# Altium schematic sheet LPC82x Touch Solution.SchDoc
size B
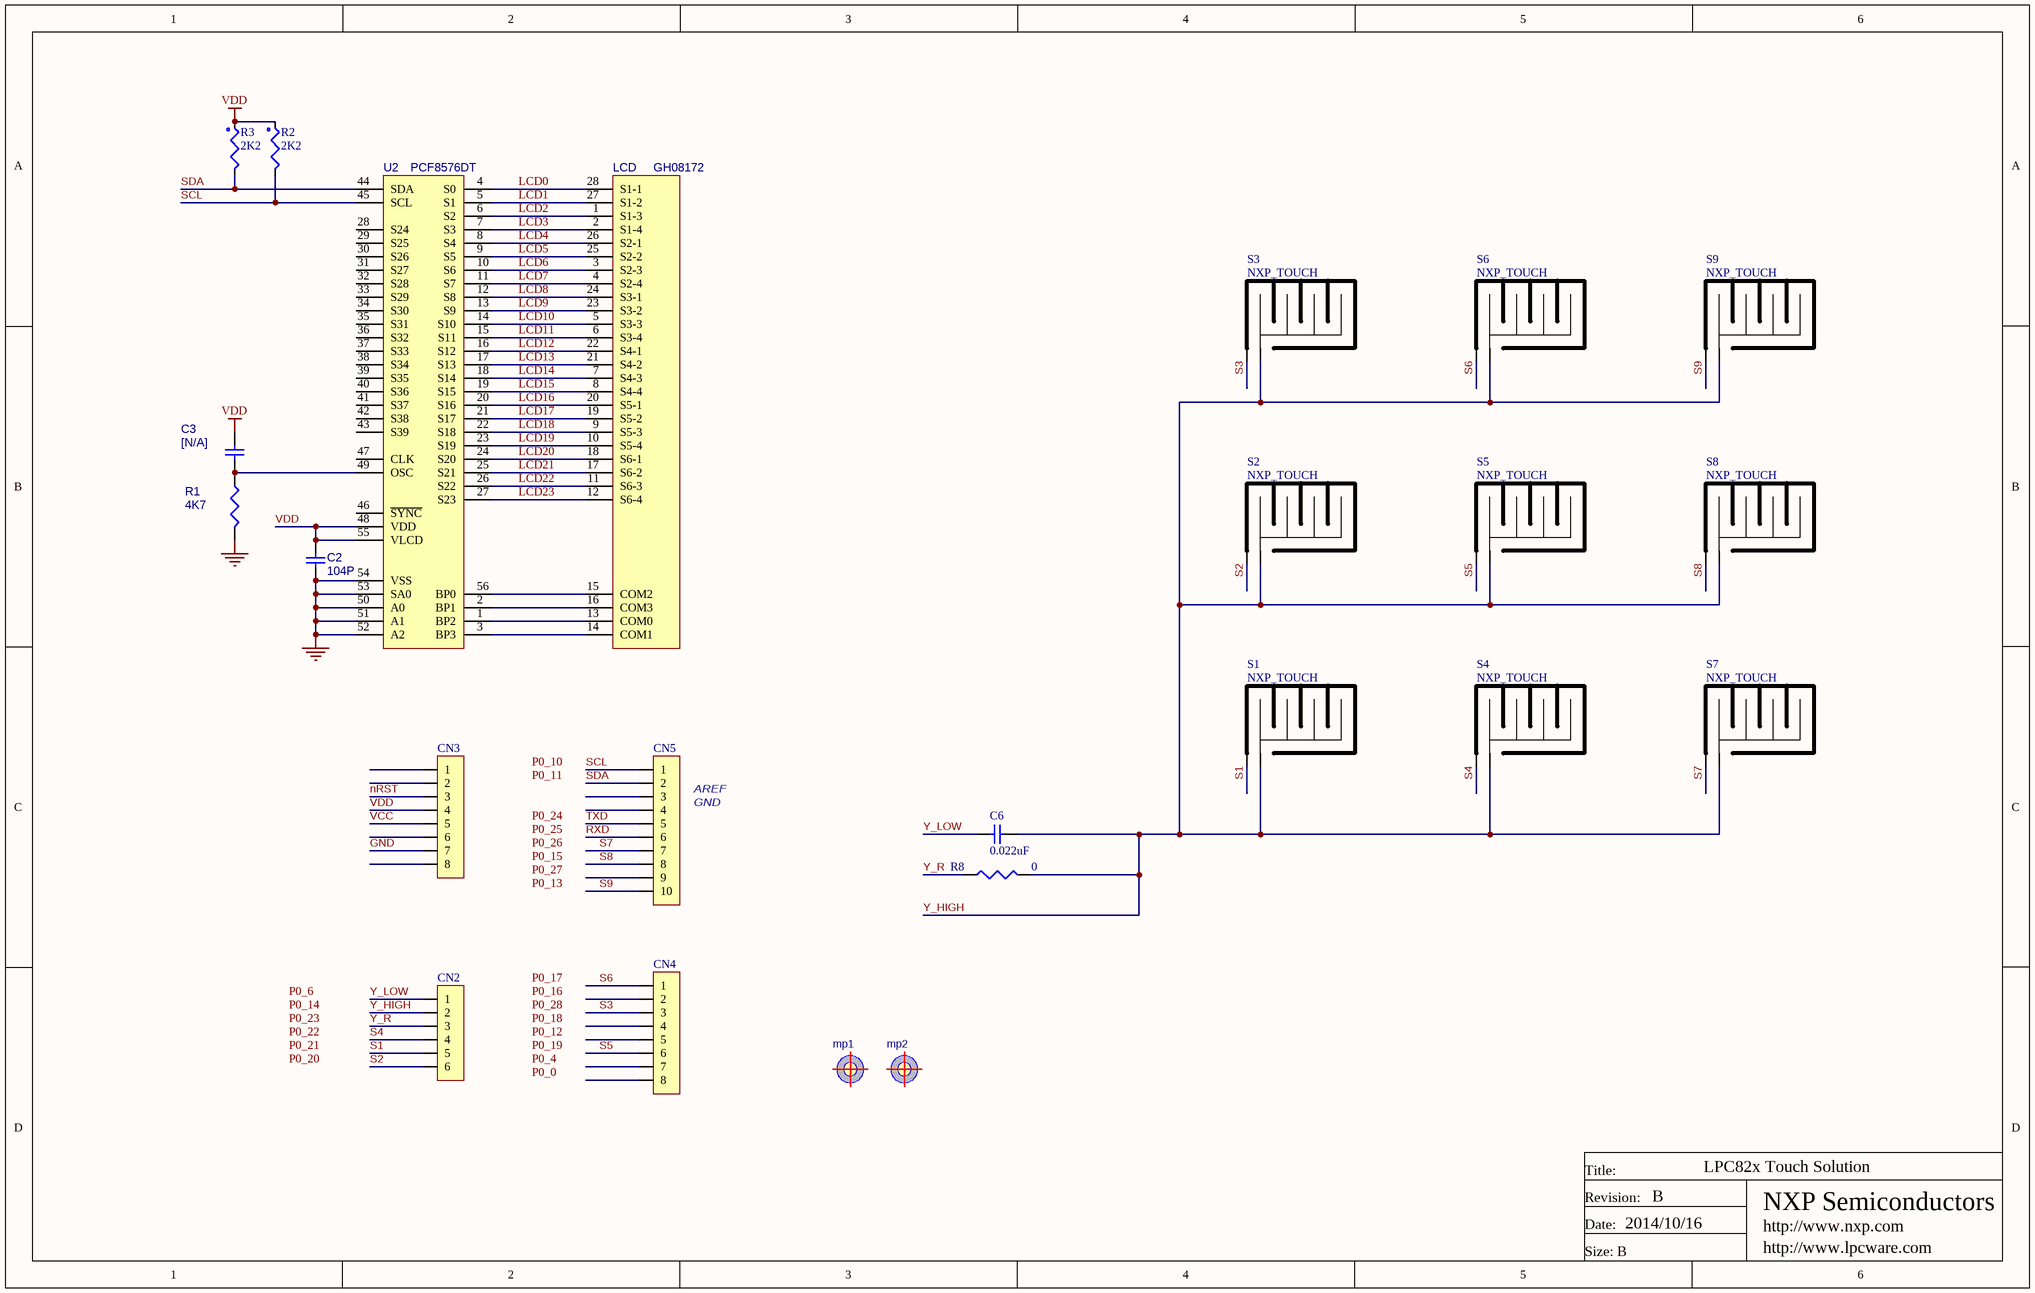
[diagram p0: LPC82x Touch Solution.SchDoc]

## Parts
C2  104P  [0603C]
C3  [N/A]  [0603C]
C6  0.022uF  [0603C]
CN2  (no value)  [SIP6]
CN3  (no value)  [SIP8]
CN4  (no value)  [SIP8]
CN5  (no value)  [SIP10]
LCD  GH08172  [GH08172]
mp1  (no value)  [MARKPOINT_0.8]
mp2  (no value)  [MARKPOINT_0.8]
R1  4K7  [0603R]
R2  2K2  [0603R]
R3  2K2  [0603R]
R8  0  [0603R]
S1  NXP_TOUCH  [SENSOR_10950x10950]
S2  NXP_TOUCH  [SENSOR_10950x10950]
S3  NXP_TOUCH  [SENSOR_10950x10950]
S4  NXP_TOUCH  [SENSOR_10950x10950]
S5  NXP_TOUCH  [SENSOR_10950x10950]
S6  NXP_TOUCH  [SENSOR_10950x10950]
S7  NXP_TOUCH  [SENSOR_10950x10950]
S8  NXP_TOUCH  [SENSOR_10950x10950]
S9  NXP_TOUCH  [SENSOR_10950x10950]
U2  PCF8576DT  [TSSOP56]

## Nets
GND: C2.2 CN3.7 R1.1 U2.50(A0) U2.51(A1) U2.52(A2) U2.53(SA0) U2.54(VSS)
VDD: C2.1 C3.1 CN3.4 R2.1(R0) R3.1(R0) U2.48(VDD) U2.55(VLCD)
LCD0: LCD.28(S1-1) U2.4(S0)
LCD1: LCD.27(S1-2) U2.5(S1)
LCD2: LCD.1(S1-3) U2.6(S2)
LCD3: LCD.2(S1-4) U2.7(S3)
LCD4: LCD.26(S2-1) U2.8(S4)
LCD5: LCD.25(S2-2) U2.9(S5)
LCD6: LCD.3(S2-3) U2.10(S6)
LCD7: LCD.4(S2-4) U2.11(S7)
LCD8: LCD.24(S3-1) U2.12(S8)
LCD9: LCD.23(S3-2) U2.13(S9)
LCD10: LCD.5(S3-3) U2.14(S10)
LCD11: LCD.6(S3-4) U2.15(S11)
LCD12: LCD.22(S4-1) U2.16(S12)
LCD13: LCD.21(S4-2) U2.17(S13)
LCD14: LCD.7(S4-3) U2.18(S14)
LCD15: LCD.8(S4-4) U2.19(S15)
LCD16: LCD.20(S5-1) U2.20(S16)
LCD17: LCD.19(S5-2) U2.21(S17)
LCD18: LCD.9(S5-3) U2.22(S18)
LCD19: LCD.10(S5-4) U2.23(S19)
LCD20: LCD.18(S6-1) U2.24(S20)
LCD21: LCD.17(S6-2) U2.25(S21)
LCD22: LCD.11(S6-3) U2.26(S22)
LCD23: LCD.12(S6-4) U2.27(S23)
nRST: CN3.3
RXD: CN5.6
S1: CN2.5 S1.X
S2: CN2.6 S2.X
S3: CN4.3 S3.X
S4: CN2.4 S4.X
S5: CN4.6 S5.X
S6: CN4.1 S6.X
S7: CN5.7 S7.X
S8: CN5.8 S8.X
S9: CN5.10 S9.X
SCL: CN5.1 R2.2(R1) U2.45(SCL)
SDA: CN5.2 R3.2(R1) U2.44(SDA)
TXD: CN5.5
VCC: CN3.5
Y_HIGH: C6.2 CN2.2 R8.2 S1.Y S2.Y S3.Y S4.Y S5.Y S6.Y S7.Y S8.Y S9.Y
Y_LOW: C6.1 CN2.1
Y_R: CN2.3 R8.1
NetC3_2: C3.2 R1.2 U2.49(OSC)
NetLCD_13: LCD.13(COM0) U2.1(BP2)
NetLCD_14: LCD.14(COM1) U2.3(BP3)
NetLCD_15: LCD.15(COM2) U2.56(BP0)
NetLCD_16: LCD.16(COM3) U2.2(BP1)

Not connected (* = marked no-connect by the designer): CN3 1 2 6 8; CN4 2 4 5 7 8; CN5 3 4 9; U2 28(S24) 29(S25) 30(S26) 31(S27) 32(S28) 33(S29) 34(S30) 35(S31) 36(S32) 37(S33) 38(S34) 39(S35) 40(S36) 41(S37) 42(S38) 43(S39) 46(~{SYNC}) 47(CLK)

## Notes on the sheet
- (near CN5) GND
- (near CN5) AREF
- LPC82x Touch Solution
- 2014/10/16
- B
- Labels drawn without touching a wire or pin: P0_0, P0_4, P0_6, P0_10, P0_11, P0_12, P0_13, P0_14, P0_15, P0_16, P0_17, P0_18, P0_19, P0_20, P0_21, P0_22, P0_23, P0_24, P0_25, P0_26, P0_27, P0_28

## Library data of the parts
C2 C3 C6 = CAP
CN2 = SIP6
CN3 CN4 = SIP8
CN5 = SIP10
mp1 mp2 = MARKPOINT
R1 R8 = RES1
R2 R3 = RES4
